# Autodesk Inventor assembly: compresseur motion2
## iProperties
Shininess: 41.0
Length Units: 11269
Angle Units: 11279
Time Units: 11290
Mass Units: 11283
Length Display Precision: 3
Angle Display Precision: 2
Created: 2002-11
Part Number: compresseur motion2
Document SubType Name: Assemblage
Designer: poste-2
Density: 0.0
Volumn: 0.0
Area: 0.0
PropertySet Name: Model Information
Control State: 0
Master: False
Checked Out: False
Author: poste-2
